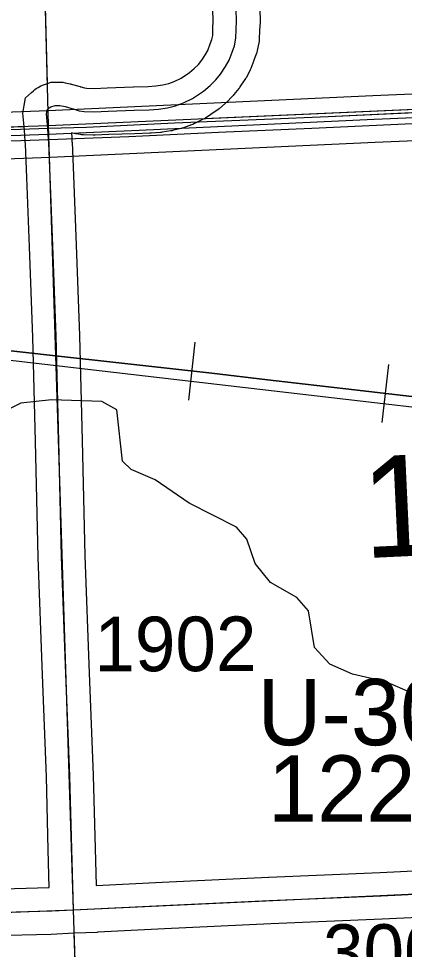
# Model space of a CAD drawing. Extents: x 128.7 to 185.5, y -21.4 to 12.6.
# Drawn here: x 158.247 to 158.743, y -10.944 to -9.75 of the extents above; entities that cross this region are included whole.
import ezdxf

# ---------------------------------------------------------------- set-up
doc = ezdxf.new("R2010")
doc.units = 0
for name, color, linetype in [('tdCoDivCarto', 7, 'Continuous'), ('tdCoHydroRiver', 7, 'Continuous'), ('tdCoPriCL', 7, 'Continuous'), ('tdCoPriDiv', 7, 'Continuous'), ('tdCoPrimary', 7, 'Continuous'), ('tdCoRRCL', 7, 'Continuous'), ('tdCoSecRdNmbr', 7, 'Continuous'), ('tdCoSecRteBand', 7, 'Continuous'), ('tdCoSecRteCL', 7, 'Continuous'), ('tdCoSectLine', 7, 'Continuous'), ('tdCoSectLinePart', 7, 'Continuous'), ('tdCoSectNmbr', 7, 'Continuous'), ('tdCoStrucSecCoName', 7, 'Continuous'), ('tdCoStrucSecFHWANum', 7, 'Continuous'), ('tdCoSurfGravel', 7, 'Continuous')]:
    doc.layers.add(name, color=color, linetype=linetype)

msp = doc.modelspace()

# ---------------------------------------------------------------- linework, layer by layer
at = {"layer": 'tdCoDivCarto'}
for p, q in [((158.6449, -9.8759), (158.5628, -9.8791)), ((158.7754, -9.8697), (158.6449, -9.8759)), ((158.3342, -9.8894), (158.2857, -9.891)), ((158.4474, -9.884), (158.3342, -9.8894)), ((158.5628, -9.8791), (158.4474, -9.884)), ((158.504, -9.8956), (158.6239, -9.8902)), ((158.6239, -9.8902), (158.7437, -9.885)), ((158.2497, -9.8922), (158.2031, -9.8936)), ((158.2497, -9.8922), (158.2031, -9.8936)), ((158.2845, -9.891), (158.2497, -9.8922)), ((158.2857, -9.891), (158.2845, -9.891)), ((158.2861, -9.9049), (158.3889, -9.9013)), ((158.3889, -9.9013), (158.504, -9.8956)), ((158.2066, -9.9077), (158.2502, -9.9062)), ((158.2502, -9.9062), (158.2855, -9.9049)), ((158.2855, -9.9049), (158.2861, -9.9049))]:
    msp.add_line(p, q, dxfattribs=at)
for points in [[(159.2191, -9.8503), (159.1458, -9.8532), (159.0804, -9.8562), (158.9917, -9.8603), (158.9662, -9.8615), (158.8533, -9.8665), (158.7754, -9.8697), (158.6449, -9.8759), (158.5628, -9.8791), (158.4474, -9.884), (158.3342, -9.8894), (158.2857, -9.891)], [(159.2191, -9.8503), (159.1458, -9.8532), (159.0804, -9.8562), (158.9917, -9.8603), (158.9662, -9.8615), (158.8533, -9.8665), (158.7754, -9.8697), (158.6449, -9.8759), (158.5628, -9.8791), (158.4474, -9.884), (158.3342, -9.8894), (158.2857, -9.891)], [(159.2191, -9.8503), (159.1458, -9.8532), (159.0804, -9.8562), (158.9917, -9.8603), (158.9662, -9.8615), (158.8533, -9.8665), (158.7754, -9.8697), (158.6449, -9.8759), (158.5628, -9.8791), (158.4474, -9.884), (158.3342, -9.8894), (158.2857, -9.891)], [(158.2861, -9.9049), (158.3889, -9.9013), (158.504, -9.8956), (158.6239, -9.8902), (158.7437, -9.885), (158.8712, -9.8791), (159.0767, -9.8702), (159.2106, -9.8648), (159.2197, -9.8644)], [(158.2861, -9.9049), (158.3889, -9.9013), (158.504, -9.8956), (158.6239, -9.8902), (158.7437, -9.885), (158.8712, -9.8791), (159.0767, -9.8702), (159.2106, -9.8648), (159.2197, -9.8644)], [(158.2861, -9.9049), (158.3889, -9.9013), (158.504, -9.8956), (158.6239, -9.8902), (158.7437, -9.885), (158.8712, -9.8791), (159.0767, -9.8702), (159.2106, -9.8648), (159.2197, -9.8644)], [(158.2497, -9.8922), (158.2031, -9.8936)], [(158.2497, -9.8922), (158.2031, -9.8936)], [(158.2857, -9.891), (158.2845, -9.891), (158.2497, -9.8922)], [(158.2857, -9.891), (158.2845, -9.891), (158.2497, -9.8922)], [(158.2857, -9.891), (158.2845, -9.891), (158.2497, -9.8922)], [(158.2036, -9.9078), (158.2066, -9.9077), (158.2502, -9.9062)], [(158.2036, -9.9078), (158.2066, -9.9077), (158.2502, -9.9062)], [(158.2036, -9.9078), (158.2066, -9.9077), (158.2502, -9.9062)], [(158.2502, -9.9062), (158.2855, -9.9049), (158.2861, -9.9049)], [(158.2502, -9.9062), (158.2855, -9.9049), (158.2861, -9.9049)], [(158.2502, -9.9062), (158.2855, -9.9049), (158.2861, -9.9049)]]:
    msp.add_lwpolyline(points, dxfattribs=at)
at = {"layer": 'tdCoHydroRiver'}
msp.add_lwpolyline([(158.7526, -10.6154), (158.7189, -10.6008), (158.676, -10.5913), (158.6471, -10.5781), (158.6274, -10.5567), (158.6194, -10.5096), (158.6046, -10.4928), (158.5707, -10.4735), (158.5509, -10.449), (158.5403, -10.4178), (158.5271, -10.4025), (158.4661, -10.3715), (158.4224, -10.3415), (158.3919, -10.3284), (158.3805, -10.3177), (158.3734, -10.2517), (158.3541, -10.2413), (158.2893, -10.2389), (158.25, -10.2435), (158.222, -10.2571)], dxfattribs=at)
at = {"layer": 'tdCoPriCL'}
msp.add_lwpolyline([(157.2675, -9.9459), (157.2809, -9.9434), (157.2816, -9.9433), (157.3314, -9.937), (157.3694, -9.9332), (157.478, -9.9286), (157.5288, -9.9265), (157.5386, -9.9261), (157.5734, -9.9247), (157.6737, -9.921), (157.6923, -9.9203), (157.748, -9.9181), (157.809, -9.916), (157.8296, -9.9156), (157.8303, -9.9156), (157.8744, -9.9134), (158.2029, -9.9007), (158.2496, -9.8995), (158.2846, -9.8982), (158.2855, -9.8981), (158.4019, -9.893), (158.7037, -9.879), (158.938, -9.8688)], dxfattribs=at)
at = {"layer": 'tdCoPriDiv'}
for points in [[(160.752, -9.7613), (160.286, -9.7745), (159.743, -9.8019), (159.3771, -9.8188), (159.2895, -9.8242), (158.7023, -9.849), (158.2853, -9.8681), (157.8731, -9.8835), (157.3673, -9.9033), (157.2762, -9.9137), (157.2295, -9.924), (157.1909, -9.9349), (157.1282, -9.9583), (157.0727, -9.9841), (156.8472, -10.0796), (156.4282, -10.2675), (156.3051, -10.3234), (156.1332, -10.3967)], [(160.7539, -9.8213), (160.2869, -9.8345), (159.746, -9.8618), (159.3804, -9.8787), (159.2923, -9.8842), (158.705, -9.909), (158.2877, -9.9281), (157.8758, -9.9434), (157.3715, -9.9632), (157.2855, -9.973), (157.245, -9.982), (157.2098, -9.9919), (157.1513, -10.0137), (157.0959, -10.0394), (156.8712, -10.1345), (156.4529, -10.3222), (156.3288, -10.3785), (156.1544, -10.4529)]]:
    msp.add_lwpolyline(points, dxfattribs=at)
at = {"layer": 'tdCoPrimary'}
msp.add_line((158.2497, -9.8922), (158.2031, -9.8936), dxfattribs=at)
msp.add_line((158.2497, -9.8922), (158.2031, -9.8936), dxfattribs=at)
for points in [[(159.2191, -9.8503), (159.1458, -9.8532), (159.0804, -9.8562), (158.9917, -9.8603), (158.9662, -9.8615), (158.8533, -9.8665), (158.7754, -9.8697), (158.6449, -9.8759), (158.5628, -9.8791), (158.4474, -9.884), (158.3342, -9.8894), (158.2857, -9.891)], [(159.2191, -9.8503), (159.1458, -9.8532), (159.0804, -9.8562), (158.9917, -9.8603), (158.9662, -9.8615), (158.8533, -9.8665), (158.7754, -9.8697), (158.6449, -9.8759), (158.5628, -9.8791), (158.4474, -9.884), (158.3342, -9.8894), (158.2857, -9.891)], [(158.2861, -9.9049), (158.3889, -9.9013), (158.504, -9.8956), (158.6239, -9.8902), (158.7437, -9.885), (158.8712, -9.8791), (159.0767, -9.8702), (159.2106, -9.8648), (159.2197, -9.8644)], [(158.2861, -9.9049), (158.3889, -9.9013), (158.504, -9.8956), (158.6239, -9.8902), (158.7437, -9.885), (158.8712, -9.8791), (159.0767, -9.8702), (159.2106, -9.8648), (159.2197, -9.8644)], [(158.7754, -9.8697), (158.6449, -9.8759), (158.5628, -9.8791), (158.4474, -9.884), (158.3342, -9.8894), (158.2857, -9.891), (158.2845, -9.891), (158.2497, -9.8922), (158.2031, -9.8936)], [(158.2066, -9.9077), (158.2502, -9.9062), (158.2855, -9.9049), (158.2861, -9.9049), (158.3889, -9.9013), (158.504, -9.8956), (158.6239, -9.8902), (158.7437, -9.885)], [(158.2857, -9.891), (158.2845, -9.891), (158.2497, -9.8922)], [(158.2857, -9.891), (158.2845, -9.891), (158.2497, -9.8922)], [(158.2036, -9.9078), (158.2066, -9.9077), (158.2502, -9.9062)], [(158.2036, -9.9078), (158.2066, -9.9077), (158.2502, -9.9062)], [(158.2502, -9.9062), (158.2855, -9.9049), (158.2861, -9.9049)], [(158.2502, -9.9062), (158.2855, -9.9049), (158.2861, -9.9049)]]:
    msp.add_lwpolyline(points, dxfattribs=at)
at = {"layer": 'tdCoRRCL'}
for p, q in [((158.4657, -10.2394), (158.474, -10.1649)), ((158.7139, -10.268), (158.7225, -10.1935))]:
    msp.add_line(p, q, dxfattribs=at)
for points in [[(157.0985, -10.056), (159.0653, -10.2844), (159.9865, -10.39), (161.3885, -10.5429), (162.2802, -10.6409), (162.9394, -10.7645), (165.7594, -11.0173), (165.9868, -11.0197), (166.2378, -10.977), (166.3926, -10.897), (167.0068, -10.5674), (167.9037, -10.0916)], [(158.7853, -10.2385), (158.6784, -10.2262), (158.5667, -10.2133), (158.4954, -10.205), (158.3719, -10.1913), (158.2983, -10.1832), (158.2026, -10.1722), (158.0975, -10.1601), (157.9999, -10.1494), (157.8972, -10.1378), (157.8072, -10.1276), (157.7892, -10.1255), (157.6961, -10.1145), (157.596, -10.1035), (157.5029, -10.0928), (157.4091, -10.0825), (157.3126, -10.0715), (157.2646, -10.0663)], [(157.2646, -10.0663), (157.3126, -10.0715), (157.4091, -10.0825), (157.5029, -10.0928), (157.596, -10.1035), (157.6961, -10.1145), (157.7892, -10.1255), (157.8072, -10.1276), (157.8972, -10.1378), (157.9999, -10.1494), (158.0975, -10.1601), (158.2026, -10.1722), (158.2983, -10.1832), (158.3719, -10.1913), (158.4954, -10.205), (158.5667, -10.2133), (158.6784, -10.2262), (158.7853, -10.2385)]]:
    msp.add_lwpolyline(points, dxfattribs=at)
at = {"layer": 'tdCoSecRteBand'}
for points in [[(158.212, -10.8669), (158.2866, -10.865), (158.2853, -10.8165), (158.2853, -10.8165), (158.2853, -10.8165), (158.2828, -10.7229), (158.2779, -10.5919), (158.2722, -10.4412), (158.2722, -10.441), (158.2722, -10.4408), (158.2688, -10.2926), (158.2653, -10.1584), (158.2611, -10.0427), (158.2575, -9.9535), (158.2558, -9.9111), (158.2555, -9.907), (158.2551, -9.9003), (158.2546, -9.8931), (158.2539, -9.884), (158.253, -9.8754), (158.2525, -9.871), (158.2534, -9.8666), (158.2543, -9.8614), (158.2562, -9.8515), (158.2636, -9.8448), (158.2663, -9.8423), (158.268, -9.8408), (158.2699, -9.8396), (158.2721, -9.8381), (158.2755, -9.8359), (158.2793, -9.8346), (158.2844, -9.8329), (158.2891, -9.8313), (158.2939, -9.8313), (158.3003, -9.8313), (158.3038, -9.8313), (158.3071, -9.8321), (158.3135, -9.8336), (158.3141, -9.8337), (158.3147, -9.8339), (158.3263, -9.8371), (158.3266, -9.8372), (158.3269, -9.8373), (158.3316, -9.8386), (158.3343, -9.8391), (158.3442, -9.8394), (158.3607, -9.8388), (158.3608, -9.8388), (158.3609, -9.8388), (158.3944, -9.8375), (158.3946, -9.8375), (158.3948, -9.8375), (158.4134, -9.837), (158.4233, -9.8362), (158.4325, -9.8348), (158.4402, -9.833), (158.447, -9.8305), (158.4558, -9.8261), (158.4666, -9.8191), (158.4726, -9.8138), (158.478, -9.8085), (158.4823, -9.8031), (158.4872, -9.7957), (158.49, -9.7906), (158.4932, -9.7822), (158.4953, -9.7766), (158.4964, -9.7714), (158.4968, -9.7624), (158.4968, -9.7623), (158.4968, -9.7623), (158.4972, -9.7526), (158.4948, -9.6805)], [(158.5547, -9.6783), (158.5572, -9.7518), (158.5572, -9.753), (158.5572, -9.7542), (158.5567, -9.765), (158.5562, -9.7763), (158.5561, -9.7786), (158.5556, -9.7809), (158.5537, -9.7908), (158.5532, -9.7931), (158.5523, -9.7954), (158.5494, -9.8033), (158.5494, -9.8034), (158.5493, -9.8035), (158.5454, -9.8138), (158.5447, -9.8157), (158.5437, -9.8175), (158.5393, -9.8256), (158.5386, -9.8268), (158.5379, -9.8279), (158.5315, -9.8375), (158.5307, -9.8387), (158.5299, -9.8397), (158.5237, -9.8474), (158.5227, -9.8486), (158.5216, -9.8497), (158.5144, -9.8569), (158.5137, -9.8576), (158.513, -9.8582), (158.5046, -9.8656), (158.503, -9.867), (158.5011, -9.8682), (158.4871, -9.8774), (158.4857, -9.8783), (158.4842, -9.879), (158.4723, -9.885), (158.4708, -9.8857), (158.4692, -9.8863), (158.4591, -9.89), (158.4574, -9.8906), (158.4556, -9.891), (158.445, -9.8935), (158.4439, -9.8938), (158.4427, -9.894), (158.4314, -9.8957), (158.4304, -9.8958), (158.4293, -9.8959), (158.4175, -9.8969), (158.4166, -9.897), (158.4158, -9.897), (158.3965, -9.8975), (158.3632, -9.8987), (158.3455, -9.8994), (158.3443, -9.8995), (158.3431, -9.8994), (158.3303, -9.899), (158.3285, -9.8989), (158.3269, -9.8986), (158.3204, -9.8976), (158.3184, -9.8973), (158.3165, -9.8968), (158.3149, -9.8963), (158.3154, -9.9028), (158.3157, -9.9073), (158.3157, -9.9078), (158.3158, -9.9082), (158.3175, -9.9511), (158.3175, -9.9511), (158.3211, -10.0404), (158.3211, -10.0404), (158.3211, -10.0405), (158.3253, -10.1564), (158.3253, -10.1565), (158.3253, -10.1567), (158.3287, -10.2911), (158.3287, -10.2911), (158.3287, -10.2912), (158.3322, -10.4392), (158.3378, -10.5896), (158.3428, -10.7208), (158.3428, -10.721), (158.3428, -10.7212), (158.3453, -10.8148), (158.3466, -10.8622)], [(158.3466, -10.8622), (158.4316, -10.8581), (158.4316, -10.8581), (158.4316, -10.8581), (158.5682, -10.8517), (158.5683, -10.8517), (158.5684, -10.8517), (158.7116, -10.8455), (158.8415, -10.8393)], [(158.8443, -10.8993), (158.7143, -10.9054), (158.7143, -10.9054), (158.7142, -10.9054), (158.571, -10.9116), (158.4345, -10.918), (158.3489, -10.9221), (158.3483, -10.9222), (158.3483, -10.9228), (158.3186, -10.9236), (158.2889, -10.925), (158.2889, -10.925), (158.2136, -10.9269), (158.0778, -10.9306), (158.0273, -10.9347), (158.0267, -10.9348), (158.026, -10.9348), (157.8813, -10.94), (157.7894, -10.9437), (157.6864, -10.9483)]]:
    msp.add_lwpolyline(points, dxfattribs=at)
at = {"layer": 'tdCoSecRteCL'}
for points in [[(158.3175, -10.8936), (158.3153, -10.8157), (158.3128, -10.722), (158.3079, -10.5908), (158.3022, -10.4401), (158.2987, -10.2919), (158.2953, -10.1575), (158.2911, -10.0416), (158.2875, -9.9523), (158.2858, -9.9094), (158.2855, -9.9049), (158.285, -9.8982), (158.2845, -9.891), (158.2838, -9.8813), (158.2828, -9.8722), (158.2838, -9.867), (158.2865, -9.8645), (158.2887, -9.8631), (158.2939, -9.8613), (158.3003, -9.8613), (158.3068, -9.8628), (158.3183, -9.866), (158.325, -9.868), (158.3314, -9.869), (158.3442, -9.8695), (158.362, -9.8687), (158.3955, -9.8675), (158.415, -9.867), (158.4268, -9.866), (158.4382, -9.8643), (158.4488, -9.8618), (158.4589, -9.8581), (158.4707, -9.8522), (158.4848, -9.8431), (158.4932, -9.8357), (158.5003, -9.8285), (158.5065, -9.8209), (158.5129, -9.8113), (158.5174, -9.8031), (158.5213, -9.7928), (158.5243, -9.7849), (158.5262, -9.775), (158.5267, -9.7637), (158.5272, -9.7528), (158.5248, -9.6793)], [(158.3175, -10.8936), (158.433, -10.888), (158.5696, -10.8816), (158.7129, -10.8755), (158.8429, -10.8693), (158.9807, -10.8631), (159.0421, -10.8602), (159.1682, -10.8533), (159.2271, -10.8508), (159.2806, -10.8493), (159.3074, -10.8475)], [(157.3138, -10.9318), (157.3793, -10.9292), (157.5013, -10.9253), (157.6281, -10.9196), (157.6851, -10.9184), (157.7881, -10.9137), (157.8801, -10.91), (158.0249, -10.9048), (158.0762, -10.9006), (158.2128, -10.8969), (158.29, -10.8949), (158.3175, -10.8936)]]:
    msp.add_lwpolyline(points, dxfattribs=at)
at = {"layer": 'tdCoSectLine'}
for points in [[(158.2596, -8.8901), (158.2852, -9.8871)], [(158.2852, -9.8871), (159.2776, -9.8428)], [(157.2808, -9.9203), (158.2852, -9.8871)], [(158.2852, -9.8871), (158.3171, -10.8936)], [(158.3171, -10.8936), (159.3071, -10.8475)], [(157.3135, -10.9318), (158.3171, -10.8936)], [(158.3171, -10.8936), (158.3496, -11.8948)]]:
    msp.add_lwpolyline(points, dxfattribs=at)
at = {"layer": 'tdCoSectLinePart'}
for points in [[(158.2596, -8.8901), (158.2838, -9.8334)], [(158.4854, -9.8782), (159.2478, -9.8441)], [(157.3113, -9.9193), (158.2539, -9.8881)], [(158.3181, -10.9236), (158.3487, -11.8648)]]:
    msp.add_lwpolyline(points, dxfattribs=at)
at = {"layer": 'tdCoSurfGravel'}
for points in [[(158.285, -9.8982), (158.2845, -9.891), (158.2838, -9.8813), (158.2828, -9.8722), (158.2838, -9.867), (158.2865, -9.8645), (158.2887, -9.8631), (158.2939, -9.8613), (158.3003, -9.8613), (158.3068, -9.8628), (158.3183, -9.866), (158.325, -9.868), (158.3314, -9.869), (158.3442, -9.8695), (158.362, -9.8687), (158.3955, -9.8675), (158.415, -9.867), (158.4268, -9.866), (158.4382, -9.8643), (158.4488, -9.8618), (158.4589, -9.8581), (158.4707, -9.8522), (158.4848, -9.8431), (158.4932, -9.8357), (158.5003, -9.8285), (158.5065, -9.8209), (158.5129, -9.8113), (158.5174, -9.8031), (158.5213, -9.7928), (158.5243, -9.7849), (158.5262, -9.775), (158.5267, -9.7637), (158.5272, -9.7528), (158.5248, -9.6793)], [(158.3175, -10.8936), (158.3153, -10.8157), (158.3128, -10.722), (158.3079, -10.5908), (158.3022, -10.4401), (158.2987, -10.2919), (158.2953, -10.1575), (158.2911, -10.0416), (158.2875, -9.9523), (158.2858, -9.9094), (158.2855, -9.9049), (158.285, -9.8982)], [(156.8232, -10.9507), (157.0175, -10.9428), (157.1963, -10.9369), (157.3046, -10.9322), (157.3138, -10.9318), (157.3793, -10.9292), (157.5013, -10.9253), (157.6281, -10.9196), (157.6851, -10.9184), (157.7881, -10.9137), (157.8801, -10.91), (158.0249, -10.9048), (158.0762, -10.9006), (158.2128, -10.8969), (158.29, -10.8949), (158.3175, -10.8936), (158.433, -10.888), (158.5696, -10.8816), (158.7129, -10.8755), (158.8429, -10.8693)]]:
    msp.add_lwpolyline(points, dxfattribs=at)

# ---------------------------------------------------------------- texts
at = {"layer": 'tdCoSecRdNmbr'}
for s, rotation, p in [('1902', 0.1191, (158.3445, -10.5875)), ('3001', 0.1193, (158.6382, -10.9822))]:
    msp.add_text(s, height=0.07, rotation=rotation, dxfattribs=at).set_placement(p)
at = {"layer": 'tdCoSectNmbr'}
msp.add_text('19', height=0.13, rotation=2.6717, dxfattribs=at).set_placement((158.6908, -10.4423))
at = {"layer": 'tdCoStrucSecCoName'}
msp.add_text('U-3070', height=0.085, dxfattribs=at).set_placement((158.554, -10.6823))
at = {"layer": 'tdCoStrucSecFHWANum'}
msp.add_text('122681', height=0.085, dxfattribs=at).set_placement((158.5673, -10.7803))

doc.saveas('drawing.dxf')
